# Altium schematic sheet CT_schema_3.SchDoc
size 282 x 169 mm
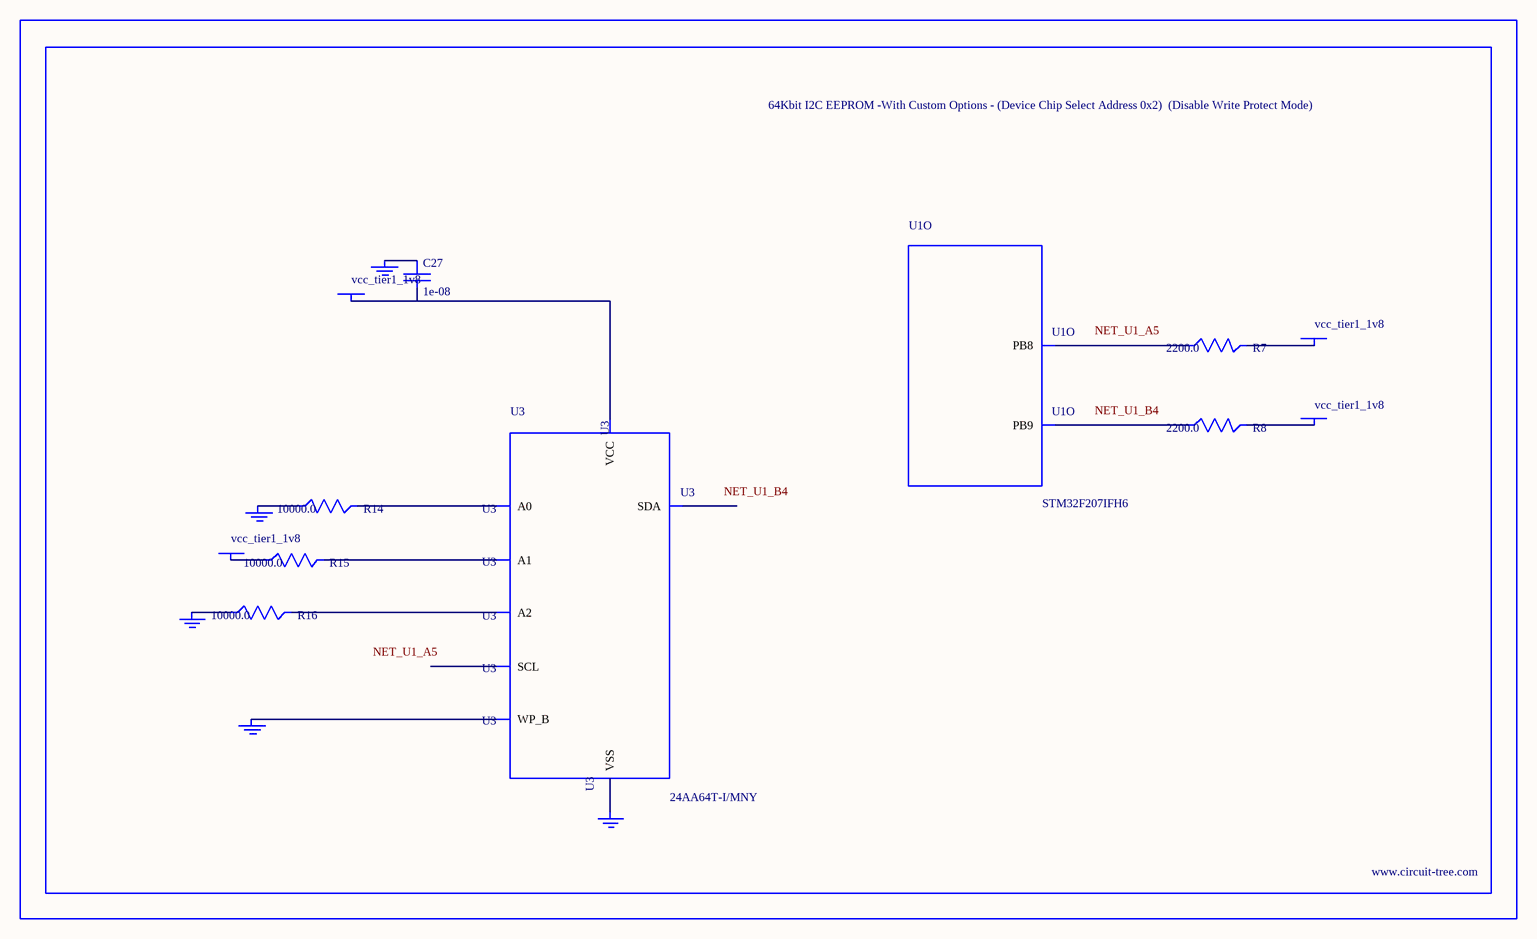
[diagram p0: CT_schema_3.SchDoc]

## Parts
BORDER2  (no value)
C27  1e-08  [C0402]
GND_INSTANCE_2_0  (no value)
GND_INSTANCE_2_1  (no value)
GND_INSTANCE_2_2  (no value)
GND_INSTANCE_2_3  (no value)
GND_INSTANCE_2_4  (no value)
POWER_INSTANCE_2_0  vcc_tier1_1v8
POWER_INSTANCE_2_1  vcc_tier1_1v8
POWER_INSTANCE_2_2  vcc_tier1_1v8
POWER_INSTANCE_2_3  vcc_tier1_1v8
R7  2200.0  [R0603]
R8  2200.0  [R0603]
R14  10000.0  [R0603]
R15  10000.0  [R0603]
R16  10000.0  [R0603]
U1  STM32F207IFH6  [UFBGA176_25]  (part O of 16)
U3  24AA64T-I/MNY  [TDFN-8/6MM]

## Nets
NetC27_1: C27.1 GND_INSTANCE_2_3.0(GND)
NetC27_2: C27.2 POWER_INSTANCE_2_1.0(PWR) U3.8(VCC)
NetGND_INSTANCE_2_0_0: GND_INSTANCE_2_0.0(GND) R14.1
NetGND_INSTANCE_2_1_0: GND_INSTANCE_2_1.0(GND) R16.1
NetGND_INSTANCE_2_2_0: GND_INSTANCE_2_2.0(GND) U3.7(WP_B)
NetGND_INSTANCE_2_4_0: GND_INSTANCE_2_4.0(GND) U3.4(VSS)
NetPOWER_INSTANCE_2_0_0: POWER_INSTANCE_2_0.0(PWR) R15.1
NetPOWER_INSTANCE_2_2_0: POWER_INSTANCE_2_2.0(PWR) R7.2
NetPOWER_INSTANCE_2_3_0: POWER_INSTANCE_2_3.0(PWR) R8.2
NetR7_1: R7.1 U1.A5(PB8)
NetR8_1: R8.1 U1.B4(PB9)
NetR14_2: R14.2 U3.1(A0)
NetR15_2: R15.2 U3.2(A1)
NetR16_2: R16.2 U3.3(A2)

Not connected (* = marked no-connect by the designer): U3 5(SDA) 6(SCL)

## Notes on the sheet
- Labels drawn without touching a wire or pin: NET_U1_A5, NET_U1_B4

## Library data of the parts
BORDER2 = BORDER_PAGE2
C27 = C0402C103K3RAC
GND_INSTANCE_2_0-GND_INSTANCE_2_4 = GND
POWER_INSTANCE_2_0-POWER_INSTANCE_2_3 = PWR
R7 R8 = RC0603JR-072K2L
R14-R16 = RC0603JR-0710KL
